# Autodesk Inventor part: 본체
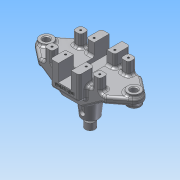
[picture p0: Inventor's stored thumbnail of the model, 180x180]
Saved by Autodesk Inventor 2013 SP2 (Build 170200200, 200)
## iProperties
Created: 2025-07
Part Number: 본체
Material: 알루미늄 6061
Document SubType Name: Modeling
Designer: a
Density: 2.71 g/cm^3
Mass: 328.838 g
Surface Area: 260.966 cm^2
Volume: 121.342 cm^3
Author: a
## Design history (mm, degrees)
sketch "스케치1"
  geometry: L1 (65, 23)-(-65, 23); L2 (-65, 23)-(-65, -23); L3 (-65, -23)-(65, -23); L4 (65, -23)-(65, 23); L5 (65, 23)-(-65, -23); L6 (-65, 23)-(65, -23); L7 (61.157, 7.88)-(41.804, 23); L8 (-61.157, 7.88)-(-41.804, 23); L9 (-61.157, -7.88)-(-41.804, -23); L10 (61.157, -7.88)-(41.804, -23); L11 (65, 0)-(-65, 0); A1 r 10 centre (55, 0) between (65, 0) and (61.157, 7.88); A2 r 10 centre (-55, 0) between (-65, 0) and (-61.157, 7.88); 3 further points
  constraints: 22 end point, 6 midpoint, 6 point on circle, 4 point on line, 4 tangent, 2 centre point, 2 horizontal alignment, 2 parallel, 2 perpendicular, 1 horizontal
  dimensions: "d0" = 130 distance of L2.end L3.end; "d2" = 46 distance of L3.end L1.start; "d3" = 20 diameter of A1; "d4" = 20 diameter of A2; "d6" = 38 deg angle of L11 L10; "d7" = 38 deg angle of L7 L11; "d8" = 38 deg angle of L11 L8; "d9" = 38 deg angle of L11 L9; "d10" = 130 distance of L11.start L11.end
extrude "돌출1" new body sketch "스케치1" distance "d11" = 9; taper "d12" = 0 deg
sketch "스케치2"
  geometry: L1 (-65, 0)-(-65, 9) reference; L2 (-65, 9)-(65, 9) reference; L3 (65, 9)-(65, 0) reference; L4 (65, 0)-(-65, 0) reference; L5 (16, -16)-(-16, -16); L6 (16, -16)-(38.85, 0); L7 (-16, -16)-(-38.85, 0); L8 (38.85, 0)-(-38.85, 0); 3 further points
  constraints: 8 end point, 2 midpoint, 2 parallel, 2 point on line, 1 vertical alignment
  dimensions: "d13" = 32 distance of L5.start L5.end; "d15" = 35 deg angle of L5 L6; "d17" = 35 deg angle of L7 L5; "d19" = 16 distance between parallel lines of L4 L5
extrude "돌출2" join sketch "스케치2" stored distance "d20" = 46; taper "d21" = 0 deg
sketch "스케치3"
  geometry: L1 (-18, -13)-(18, -13); L2 (18, -13)-(18, -32); L3 (18, -32)-(-18, -32); L4 (-18, -32)-(-18, -13); L5 (-18, 32)-(18, 32); L6 (18, 32)-(18, 13); L7 (18, 13)-(-18, 13); L8 (-18, 13)-(-18, 32); 3 further points
  constraints: 16 end point, 4 parallel, 2 horizontal, 2 midpoint, 2 perpendicular, 2 vertical alignment
  dimensions: "d22" = 36 distance of L2.end L3.end; "d24" = 36 distance of L5.start L5.end; "d25" = 64 distance between parallel lines of L3 L5; "d26" = 32 distance from line of point (0, 0) L5; "d27" = 26 distance between parallel lines of L1 L7; "d28" = 13 distance from line of point (0, 0) L7
extrude "돌출3" join sketch "스케치3" distance "d29" = 16; taper "d31" = 0 deg; dims "d30" = 15, "d32" = 0
sketch "스케치4"
  geometry: L1 (-35, 13)-(-25, 13); L2 (-25, 13)-(-25, 23); L3 (-25, 23)-(-35, 23); L4 (-35, 23)-(-35, 13); L5 (-35, 13)-(-25, 23); L6 (-25, 13)-(-35, 23); 2 further points
  constraints: 12 end point, 2 midpoint, 2 parallel, 1 horizontal, 1 perpendicular
  dimensions: "d33" = 10 distance of L2.end L3.end; "d35" = 10 distance of L3.end L1.start; "d36" = 30 horizontal distance of point (0, 0) point (-30, 18); "d37" = 18 vertical distance of point (0, 0) point (-30, 18)
extrude "돌출4" join sketch "스케치4" distance "d38" = 16; taper "d39" = 0 deg
sketch "스케치5"
  geometry: L1 (0, 0)-(36, 0) reference; L2 (10, 0)-(26, 0); L3 (26, 0)-(26, -21); L4 (26, -21)-(10, -21); L5 (10, -21)-(10, 0); 2 further points
  constraints: 8 end point, 2 parallel, 1 collinear, 1 horizontal, 1 midpoint, 1 perpendicular, 1 vertical alignment
  dimensions: "d46" = 16 distance of L2.start L2.end; "d48" = 21 distance of L2.end L3.end
extrude "돌출5" cut sketch "스케치5" stored distance "d49" = 16; taper "d50" = 0 deg
sketch "스케치6"
  geometry: C1 r 8 at (-55, 0); A1 r 10 centre (-55, 0) between (-61.157, 7.88) and (-61.157, -7.88) reference; 1 further point
  constraints: 1 centre point, 1 coincident
  dimensions: "d51" = 16 diameter of C1
extrude "돌출6" join sketch "스케치6" distance "d52" = 3; taper "d53" = 0 deg
sketch "스케치7"
  geometry: C1 r 8 at (-55, 0); A1 r 10 centre (-55, 0) between (-61.157, 7.88) and (-61.157, -7.88) reference; 1 further point
  constraints: 1 centre point, 1 coincident
  dimensions: "d54" = 16 diameter of C1
extrude "돌출7" join sketch "스케치7" distance "d55" = 3; taper "d56" = 0 deg
sketch "스케치8"
  geometry: L1 (38.85, 0)-(16, -16) reference; L2 (16, -16)-(-16, -16) reference; L3 (-16, -16)-(-38.85, 0) reference; L4 (-38.85, 0)-(-47, 0) reference; L5 (-47, 0)-(-47, -3) reference; L6 (-47, -3)-(-63, -3) reference; L7 (-63, -3)-(-63, 0) reference; L8 (-63, 0)-(-65, 0) reference; L9 (-65, 0)-(-65, 9) reference; L10 (-65, 9)-(-63, 9) reference; L11 (-63, 9)-(-63, 12) reference; L12 (-63, 12)-(-47, 12) reference; L13 (-47, 12)-(-47, 9) reference; L14 (-47, 9)-(-8, 9) reference; L15 (-8, 9)-(-8, 4) reference; L16 (-8, 4)-(8, 4) reference; L17 (8, 4)-(8, 9) reference; L18 (8, 9)-(47, 9) reference; L19 (47, 9)-(47, 12) reference; L20 (47, 12)-(63, 12) reference; L21 (63, 12)-(63, 9) reference; L22 (63, 9)-(65, 9) reference; L23 (65, 9)-(65, 0) reference; L24 (65, 0)-(63, 0) reference; L25 (63, 0)-(63, -3) reference; L26 (63, -3)-(47, -3) reference; L27 (47, -3)-(47, 0) reference; L28 (47, 0)-(38.85, 0) reference; L29 (0, -16)-(0, -57); L30 (-12.5, -16)-(-12.5, -20); L31 (-12.5, -20)-(-10, -43); L32 (-10, -43)-(-4.7, -43); L33 (-4.7, -43)-(-4.7, -46); L34 (-4.7, -57)-(0, -57); L35 (-12.5, -16)-(0, -16); L36 (-6, -48.252)-(-6, -56.249); L37 (-4.7, -46)-(-6, -48.252); L38 (-4.7, -57)-(-6, -56.249); 1 further point
  constraints: 20 end point, 5 perpendicular, 3 parallel, 1 midpoint, 1 point on line
  dimensions: "d57" = 41 distance of L29.start L29.end; "d59" = 4 distance of L30.start L30.end; "d60" = 23 vertical distance of L31.end L30.end; "d61" = 3 distance of L32.end L33.end; "d62" = 25 diameter of L30 L29; "d63" = 20 diameter of L31.end L29; "d65" = 9.4 diameter of L33 L29; "d66" = 9.4 diameter of L34.start L29; "d130" = 30 deg angle of L36 L37; "d131" = 12 diameter of L36 L29
revolve "회전1" sketch "스케치8" stored, may be unused: angle "d67" = 90 deg
sketch "스케치9"
  geometry: L1 (-6, 23)-(-6, 32) reference; L2 (-6, 32)-(4, 32) reference; L3 (4, 32)-(4, -32) reference; L4 (4, -32)-(-6, -32) reference; L5 (-6, -32)-(-6, -23) reference; L6 (-6, -23)-(-16, -23) reference; L7 (-16, -23)-(-16, -12.5) reference; L8 (-16, -12.5)-(-20, -12.5) reference; L9 (-20, -12.5)-(-43, -10) reference; L10 (-43, -10)-(-43, -4.7) reference; L11 (-43, -4.7)-(-46, -4.7) reference; L12 (-57, -4.7)-(-57, 4.7) reference; L13 (-46, 4.7)-(-43, 4.7) reference; L14 (-43, 4.7)-(-43, 10) reference; L15 (-43, 10)-(-20, 12.5) reference; L16 (-20, 12.5)-(-16, 12.5) reference; L17 (-16, 12.5)-(-16, 23) reference; L18 (-16, 23)-(-6, 23) reference; L19 (-26.597, 11.783)-(-26.164, 7.806); L20 (-26.164, 7.806)-(-35.112, 6.834); L21 (-35.112, 6.834)-(-35.544, 10.81); L22 (-26.597, 11.783)-(-35.544, 10.81); L23 (-46, -4.7)-(-48.252, -6) reference; L24 (-48.252, -6)-(-56.249, -6) reference; L25 (-56.249, -6)-(-57, -4.7) reference; L26 (-57, 4.7)-(-56.249, 6) reference; L27 (-56.249, 6)-(-48.252, 6) reference; L28 (-48.252, 6)-(-46, 4.7) reference; 1 further point
  constraints: 8 end point, 4 perpendicular, 2 point on line
  dimensions: "d68" = 9 distance between parallel lines of L21 L19; "d70" = 7.5 distance from line of L21 L14.end; "d71" = 4 distance between parallel lines of L22 L20
extrude "돌출8" cut sketch "스케치9" stored distance "d72" = 7; taper "d73" = 0 deg
sketch "스케치10"
  geometry: L1 (7, 0)-(0, 0) reference; L2 (0, 0)-(0, -9) reference; L3 (7, -9)-(0, -9) reference; C1 r 3.5 at (3.5, 0); 2 further points
  constraints: 2 midpoint, 1 centre point, 1 horizontal alignment, 1 tangent, 2 other
extrude "돌출9" cut sketch "스케치10" distance "d74" = 4; taper "d75" = 0 deg
sketch "스케치11"
  geometry: C1 r 8 at (0, 0) reference; C2 r 4 at (0, 0); 1 further point
  constraints: 1 centre point, 1 coincident
  dimensions: "d76" = 8 diameter of C2
extrude "돌출10" cut sketch "스케치11" stored distance "d77" = 4; taper "d78" = 0 deg
sketch "스케치12"
  geometry: 2 further points
  dimensions: "d79" = 30 horizontal distance of point (0, 0) point (-30, 18); "d80" = 18 vertical distance of point (0, 0) point (-30, 18)
hole "구멍1" sketch "스케치12" at (-30, 18) diameter "d81" = 2.459; stored, may be unused: countersink angle "d85" = 90 deg, drill point angle "d87" = 118 deg; dims "d82" = 6, "d83" = 4, "d84" = 2, "d86" = 8
sketch "스케치13"
  geometry: 2 further points
  dimensions: "d94" = 13 horizontal distance of point (0, 0) point (-13, 18); "d95" = 18 vertical distance of point (0, 0) point (-13, 18)
hole "구멍2" sketch "스케치13" at (-13, 18) diameter "d96" = 2.459; stored, may be unused: countersink angle "d100" = 90 deg, drill point angle "d102" = 118 deg; dims "d97" = 6, "d98" = 4, "d99" = 2, "d101" = 8
fillet "모깎기1" dims "d109" = 3
fillet "모깎기2" dims "d110" = 3
fillet "모깎기3" dims "d111" = 3
fillet "모깎기4" dims "d112" = 3
fillet "모깎기5" dims "d113" = 3
fillet "모깎기6" dims "d114" = 3
fillet "모깎기8" dims "d116" = 3
fillet "모깎기9" dims "d117" = 3
fillet "모깎기10" dims "d118" = 3
fillet "모깎기12" dims "d120" = 3
fillet "모깎기13" dims "d121" = 3
fillet "모깎기14" dims "d122" = 3
fillet "모깎기15" dims "d123" = 3
chamfer "모따기1" distance "d124" = 1; stored, may be unused: second distance "d125" = 2, angle "d126" = 45 deg
sketch "스케치14"
  geometry: 3 further points
  constraints: 1 vertical alignment, 1 other
  dimensions: "d127" = 24 vertical distance of point (0, 21) point (8, -3)
feature "엠보싱1" sketch "스케치14" dims "d128" = 0.5, "d129" = 0
node "솔리드1"
pattern_linear "직사각형 패턴1" dims "d42" = 60, "d45" = 36
mirror "대칭1"
mirror "대칭2"
pattern_linear "직사각형 패턴2" dims "d90" = 60, "d93" = 36
pattern_linear "직사각형 패턴3" dims "d105" = 26, "d108" = 36
node "절단 모서리 투영1"
node "절단 모서리 투영2"
node "절단 모서리 투영3"
